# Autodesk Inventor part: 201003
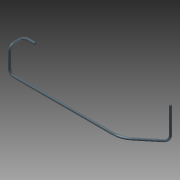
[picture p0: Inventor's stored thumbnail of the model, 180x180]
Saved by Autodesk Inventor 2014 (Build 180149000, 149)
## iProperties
Created: 2007-12
Part Number: 201003
Document SubType Name: Modeling
Designer: MM
Density: 7.85 g/cm^3
Material: Steel
Description: SIDE MOUNTING BAR
Mass: 75.8289 g
Surface Area: 77.6706 cm^2
Volume: 9.65974 cm^3
Appearance: Lead
Component Category: Lower Component
Author: MM
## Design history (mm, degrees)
workplane "Work Plane1"
workplane "Work Plane2"
workplane "Work Plane3"
sketch "Sketch2"
  geometry: L1 (0, 0)-(-60, -50); L2 (-60, -50)-(-310, -50); L3 (-310, 10)-(-310, -60) reference; 3 further points
  constraints: 4 end point, 3 coincident, 1 horizontal, 1 point on line
  dimensions: "d3" = 250 distance of L1.end L2.end; "d4" = 50 distance from line of point (0, 0) L2
sketch "Sketch3"
  geometry: L1 (-50, -70)-(-50, -15); L2 (-50, -15)-(-17.5, -15); 2 further points
  constraints: 4 end point, 2 coincident, 1 perpendicular, 1 vertical
  dimensions: "d5" = 55 distance of L1.start L1.end; "d6" = 32.5 distance of L1.end L2.end
workplane "Work Plane4"
sketch "Sketch4"
  geometry: L1 (0, 0)-(-25, 0); 1 further point
  constraints: 2 end point, 1 coincident, 1 horizontal
  dimensions: "d7" = 25 distance of L1.start L1.end
sketch "3D Sketch1" dims "d8" = 10, "d12" = 50
  geometry: L1 through (-40, -25) direction (-1, 0); L2 through (-50, -60) direction (-7.11e-17, 1); L3 through (-6.402, -60) direction (-0.64, 0.768); 21 other entities
  constraints: 2 horizontal, 2 vertical, 2 other
  dimensions: "d9" = 10 dimension on L1 (= d8); "d10" = 10 dimension on L2 (= d8); "d11" = 10 dimension on L3 (= d8)
sketch "Sketch5"
  geometry: C1 r 2.5 at (0, 0); 1 further point
  constraints: 1 centre point, 1 coincident
  dimensions: "d13" = 5 diameter of C1
sweep "Sweep1" sketch "3D Sketch1", "Sketch5" dims "d14" = 0
body "Solid1"
